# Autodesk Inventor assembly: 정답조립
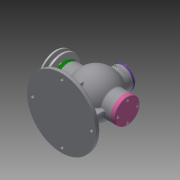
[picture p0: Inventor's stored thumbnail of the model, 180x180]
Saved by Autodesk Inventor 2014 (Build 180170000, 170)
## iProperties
Created: 2020-08
Part Number: 정답조립
Document SubType Name: Assembly
Designer: kh
Author: kh
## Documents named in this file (18)
- C:\Users\kh\Desktop\700806V1031\답안조립품.iam
- C:\Users\kh\Desktop\700806V1031\본체.ipt
- C:\Users\kh\Desktop\700806V1031\V-벨트풀리.ipt
- C:\Users\kh\Desktop\700806V1031\너트 M8.ipt
- C:\Users\kh\Desktop\700806V1031\뒤커버.ipt
- C:\Users\kh\Desktop\700806V1031\멈춤링 15x1.ipt
- C:\Users\kh\Desktop\700806V1031\멈춤링 35x1.6.ipt
- 멈춤링 35x1.6.ipt
- C:\Users\kh\Desktop\700806V1031\베어링 6202.ipt
- 베어링 6202.ipt
- C:\Users\kh\Desktop\700806V1031\볼트 M4.ipt
- C:\Users\kh\Desktop\700806V1031\상부커버.ipt
- C:\Users\kh\Desktop\700806V1031\슬라이드.ipt
- C:\Users\kh\Desktop\700806V1031\앞커버.ipt
- C:\Users\kh\Desktop\700806V1031\오일 실 15 30 7.ipt
- C:\Users\kh\Desktop\700806V1031\칼라.ipt
- C:\Users\kh\Desktop\700806V1031\키 3x3x12.ipt
- C:\Users\kh\Desktop\700806V1031\편심축.ipt
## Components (1 placed, 1 different names)
1. V-벨트풀리:1 — Insert:16, Mate:2, Insert:19
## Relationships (3: Insert 2, Mate 1)
- Insert:16: V-벨트풀리:1
- Mate:2: V-벨트풀리:1
- Insert:19: V-벨트풀리:1
